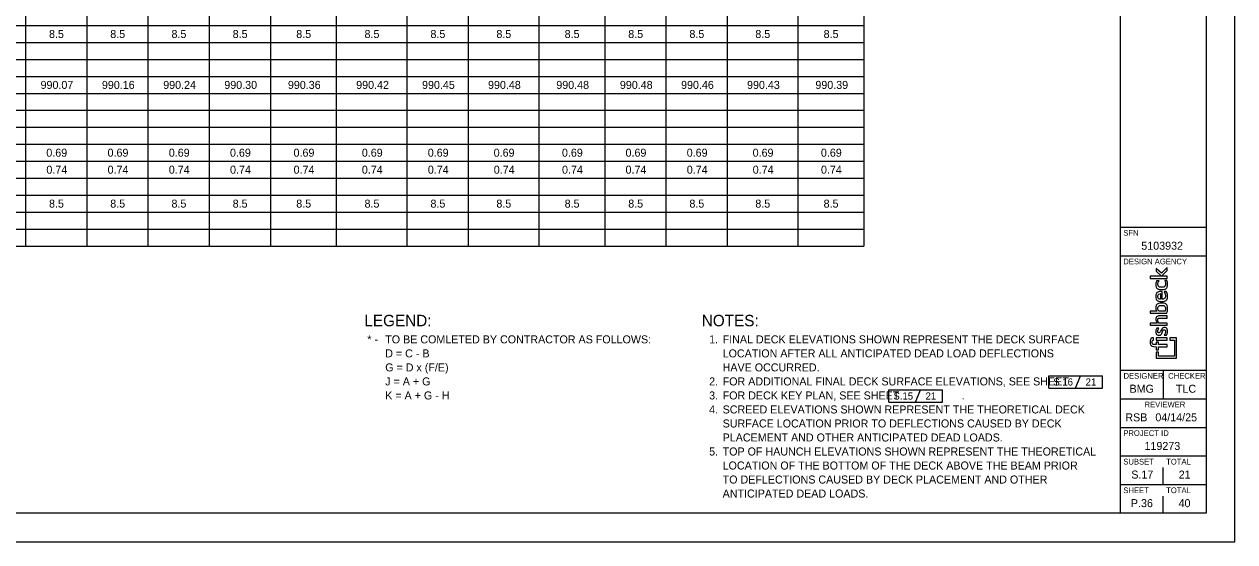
# Model space of a CAD drawing. Extents: x 0 to 34, y 0 to 22.
# Drawn here: x 12.83 to 34, y 0 to 9.05 of the extents above; entities that cross this region are included whole.
import ezdxf

# ---------------------------------------------------------------- set-up
doc = ezdxf.new("R2010")
doc.units = 0
for name, color, linetype in [('BR_P_Gen_Text', 7, 'Continuous'), ('SH_Border', 7, 'Continuous'), ('SH_Cut_Line', 7, 'Continuous'), ('SH_Data', 7, 'Continuous')]:
    doc.layers.add(name, color=color, linetype=linetype)

msp = doc.modelspace()

# ---------------------------------------------------------------- linework, layer by layer
at = {"layer": 'BR_P_Gen_Text'}
for p, q in [((27.51, 20.916), (27.51, 5.17)), ((12.851, 20.57), (12.851, 5.17)), ((13.921, 20.273), (13.921, 5.17)), ((14.992, 20.273), (14.992, 5.17)), ((16.063, 20.273), (16.063, 5.17)), ((17.133, 20.273), (17.133, 5.17)), ((18.286, 20.273), (18.286, 5.17)), ((19.521, 20.273), (19.521, 5.17)), ((20.592, 20.273), (20.592, 5.17)), ((21.827, 20.273), (21.827, 5.17)), ((22.98, 20.273), (22.98, 5.17)), ((24.051, 20.273), (24.051, 5.17)), ((25.121, 20.273), (25.121, 5.17)), ((26.357, 20.273), (26.357, 5.17)), ((6.641, 9.024), (27.51, 9.024)), ((6.641, 8.728), (27.51, 8.728)), ((6.641, 8.431), (27.51, 8.431)), ((6.131, 8.135), (27.51, 8.135)), ((6.641, 7.838), (27.51, 7.838)), ((6.641, 7.542), (27.51, 7.542)), ((6.641, 7.245), (27.51, 7.245)), ((6.641, 6.949), (27.51, 6.949)), ((6.641, 6.652), (27.51, 6.652)), ((6.641, 6.356), (27.51, 6.356)), ((6.641, 6.059), (27.51, 6.059)), ((6.641, 5.763), (27.51, 5.763)), ((6.641, 5.466), (27.51, 5.466)), ((6.131, 5.17), (27.51, 5.17)), ((30.746, 2.903), (31.688, 2.903)), ((30.746, 2.685), (30.746, 2.903)), ((31.212, 2.685), (31.302, 2.903)), ((31.688, 2.685), (31.688, 2.903)), ((27.947, 2.657), (28.89, 2.657)), ((27.947, 2.44), (27.947, 2.657)), ((28.414, 2.44), (28.504, 2.657)), ((28.89, 2.44), (28.89, 2.657)), ((30.746, 2.685), (31.688, 2.685)), ((27.947, 2.44), (28.89, 2.44))]:
    msp.add_line(p, q, dxfattribs=at)
at = {"layer": 'SH_Border'}
for p, q in [((32, 0.5), (32, 21.5)), ((32, 5.5), (33.5, 5.5)), ((32, 5), (33.5, 5)), ((32, 3), (33.5, 3)), ((32.75, 3), (32.75, 2.5)), ((32, 2.5), (33.5, 2.5)), ((32, 2), (33.5, 2)), ((32, 1.5), (33.5, 1.5)), ((32, 1), (33.5, 1))]:
    msp.add_line(p, q, dxfattribs=at)
msp.add_lwpolyline([(1.5, 21.5), (33.5, 21.5), (33.5, 0.5), (1.5, 0.5)], close=True, dxfattribs=at)
at = {"layer": 'SH_Cut_Line'}
msp.add_lwpolyline([(0, 0), (34, 0), (34, 22), (0, 22)], close=True, dxfattribs=at)
at = {"layer": 'SH_Data'}
for p, q in [((32.623, 4.777), (32.623, 4.73)), ((32.72, 4.693), (32.623, 4.777)), ((32.623, 4.73), (32.72, 4.643)), ((32.82, 4.794), (32.72, 4.693)), ((32.72, 4.643), (32.82, 4.742)), ((32.82, 4.742), (32.82, 4.794)), ((32.522, 4.642), (32.522, 4.603)), ((32.82, 4.642), (32.522, 4.642)), ((32.522, 4.603), (32.82, 4.603)), ((32.675, 4.562), (32.633, 4.562)), ((32.812, 4.566), (32.774, 4.566)), ((32.82, 4.603), (32.82, 4.642)), ((32.702, 4.337), (32.702, 4.239)), ((32.727, 4.238), (32.727, 4.376)), ((32.8, 4.372), (32.763, 4.372)), ((32.781, 4.033), (32.675, 4.033)), ((32.75, 4), (32.75, 4)), ((32.674, 3.735), (32.636, 3.735)), ((32.764, 3.611), (32.806, 3.611)), ((32.58, 3.527), (32.58, 3.566)), ((32.623, 3.566), (32.623, 3.527)), ((32.82, 3.566), (32.623, 3.566)), ((32.623, 3.527), (32.82, 3.527)), ((32.82, 3.527), (32.82, 3.566)), ((32.982, 3.566), (32.863, 3.566)), ((32.863, 3.566), (32.863, 3.527)), ((32.863, 3.527), (32.943, 3.527)), ((32.943, 3.527), (32.943, 3.246)), ((32.982, 3.207), (32.982, 3.566)), ((32.663, 3.313), (32.624, 3.313)), ((32.624, 3.313), (32.624, 3.207)), ((32.624, 3.207), (32.982, 3.207)), ((32.663, 3.246), (32.663, 3.313)), ((32.943, 3.246), (32.663, 3.246)), ((32.75, 1), (32.75, 1.3)), ((32.375, 0.675), (32.375, 0.675)), ((32.75, 0.5), (32.75, 0.8))]:
    msp.add_line(p, q, dxfattribs=at)
for points in [[(32.637, 4.033), (32.522, 4.033), (32.522, 3.994), (32.809, 3.994)], [(32.649, 3.824), (32.649, 3.823), (32.522, 3.823), (32.522, 3.784), (32.82, 3.784), (32.82, 3.823), (32.679, 3.823)], [(32.698, 3.911), (32.82, 3.911), (32.82, 3.949), (32.699, 3.949)], [(32.623, 3.409), (32.623, 3.357), (32.663, 3.357), (32.663, 3.409), (32.82, 3.409), (32.82, 3.448), (32.663, 3.448), (32.663, 3.492), (32.623, 3.492), (32.623, 3.448)]]:
    msp.add_lwpolyline(points, dxfattribs=at)
for points in [[(32.633, 4.562), (32.625, 4.543), (32.62, 4.528), (32.62, 4.505), (32.62, 4.446), (32.661, 4.408), (32.725, 4.408), (32.783, 4.408), (32.824, 4.449), (32.824, 4.508), (32.824, 4.528), (32.818, 4.553), (32.812, 4.566)], [(32.774, 4.566), (32.782, 4.547), (32.787, 4.531), (32.787, 4.514), (32.787, 4.474), (32.762, 4.448), (32.722, 4.448), (32.682, 4.448), (32.655, 4.472), (32.655, 4.508), (32.655, 4.525), (32.66, 4.54), (32.675, 4.562)], [(32.727, 4.376), (32.655, 4.376), (32.62, 4.343), (32.62, 4.291), (32.62, 4.236), (32.66, 4.199), (32.719, 4.199), (32.773, 4.199), (32.824, 4.233), (32.824, 4.294), (32.824, 4.327), (32.816, 4.349), (32.8, 4.372)], [(32.702, 4.239), (32.671, 4.244), (32.653, 4.262), (32.653, 4.291), (32.653, 4.319), (32.672, 4.336), (32.702, 4.337)], [(32.763, 4.372), (32.778, 4.35), (32.786, 4.327), (32.786, 4.304), (32.786, 4.266), (32.766, 4.244), (32.727, 4.238)], [(32.809, 3.994), (32.818, 4.013), (32.824, 4.041), (32.824, 4.067), (32.824, 4.133), (32.784, 4.172), (32.717, 4.172), (32.661, 4.172), (32.62, 4.136), (32.62, 4.087), (32.62, 4.068), (32.625, 4.05), (32.637, 4.033)], [(32.675, 4.033), (32.66, 4.05), (32.654, 4.061), (32.654, 4.078), (32.654, 4.11), (32.682, 4.132), (32.723, 4.132), (32.76, 4.132), (32.787, 4.107), (32.787, 4.072), (32.787, 4.061), (32.784, 4.044), (32.781, 4.033)], [(32.699, 3.949), (32.646, 3.949), (32.62, 3.921), (32.62, 3.883), (32.62, 3.861), (32.63, 3.839), (32.649, 3.824)], [(32.679, 3.823), (32.658, 3.842), (32.651, 3.855), (32.651, 3.872), (32.651, 3.896), (32.669, 3.911), (32.698, 3.911)], [(32.636, 3.735), (32.625, 3.714), (32.62, 3.695), (32.62, 3.677), (32.62, 3.638), (32.64, 3.612), (32.673, 3.612), (32.726, 3.612), (32.74, 3.704), (32.767, 3.704), (32.781, 3.704), (32.789, 3.691), (32.789, 3.675), (32.789, 3.659), (32.781, 3.636), (32.764, 3.611)], [(32.806, 3.611), (32.819, 3.636), (32.824, 3.655), (32.824, 3.679), (32.824, 3.716), (32.8, 3.744), (32.766, 3.744), (32.746, 3.744), (32.732, 3.732), (32.711, 3.7), (32.691, 3.665), (32.68, 3.652), (32.672, 3.652), (32.661, 3.652), (32.654, 3.662), (32.654, 3.678), (32.654, 3.692), (32.66, 3.713), (32.674, 3.735)], [(32.58, 3.566), (32.542, 3.565), (32.518, 3.536), (32.518, 3.492), (32.518, 3.439), (32.551, 3.408), (32.623, 3.409)], [(32.623, 3.448), (32.576, 3.445), (32.553, 3.461), (32.553, 3.492), (32.553, 3.509), (32.561, 3.52), (32.58, 3.527)]]:
    msp.add_open_spline(points, degree=3, dxfattribs=at)

# ---------------------------------------------------------------- texts
at = {"layer": 'BR_P_Gen_Text'}
for s, height, p in [('8.5', 0.14, (13.262, 8.806)), ('8.5', 0.14, (14.333, 8.806)), ('8.5', 0.14, (15.404, 8.806)), ('8.5', 0.14, (16.474, 8.806)), ('8.5', 0.14, (17.586, 8.806)), ('8.5', 0.14, (18.78, 8.806)), ('8.5', 0.14, (19.933, 8.806)), ('8.5', 0.14, (21.086, 8.806)), ('8.5', 0.14, (22.28, 8.806)), ('8.5', 0.14, (23.392, 8.806)), ('8.5', 0.14, (24.462, 8.806)), ('8.5', 0.14, (25.615, 8.806)), ('8.5', 0.14, (26.809, 8.806)), ('990.07', 0.14, (13.114, 7.916)), ('990.16', 0.14, (14.187, 7.916)), ('990.24', 0.14, (15.259, 7.916)), ('990.30', 0.14, (16.328, 7.916)), ('990.36', 0.14, (17.44, 7.916)), ('990.42', 0.14, (18.634, 7.916)), ('990.45', 0.14, (19.786, 7.916)), ('990.48', 0.14, (20.94, 7.916)), ('990.48', 0.14, (22.134, 7.916)), ('990.48', 0.14, (23.246, 7.916)), ('990.46', 0.14, (24.316, 7.916)), ('990.43', 0.14, (25.47, 7.916)), ('990.39', 0.14, (26.665, 7.916)), ('0.69', 0.14, (13.215, 6.731)), ('0.69', 0.14, (14.286, 6.731)), ('0.69', 0.14, (15.357, 6.731)), ('0.69', 0.14, (16.427, 6.731)), ('0.69', 0.14, (17.539, 6.731)), ('0.69', 0.14, (18.733, 6.731)), ('0.69', 0.14, (19.886, 6.731)), ('0.69', 0.14, (21.039, 6.731)), ('0.69', 0.14, (22.233, 6.731)), ('0.69', 0.14, (23.345, 6.731)), ('0.69', 0.14, (24.415, 6.731)), ('0.69', 0.14, (25.568, 6.731)), ('0.69', 0.14, (26.762, 6.731)), ('0.74', 0.14, (13.216, 6.434)), ('0.74', 0.14, (14.287, 6.434)), ('0.74', 0.14, (15.357, 6.434)), ('0.74', 0.14, (16.428, 6.434)), ('0.74', 0.14, (17.54, 6.434)), ('0.74', 0.14, (18.734, 6.434)), ('0.74', 0.14, (19.887, 6.434)), ('0.74', 0.14, (21.04, 6.434)), ('0.74', 0.14, (22.234, 6.434)), ('0.74', 0.14, (23.345, 6.434)), ('0.74', 0.14, (24.416, 6.434)), ('0.74', 0.14, (25.569, 6.434)), ('0.74', 0.14, (26.763, 6.434)), ('8.5', 0.14, (13.262, 5.841)), ('8.5', 0.14, (14.333, 5.841)), ('8.5', 0.14, (15.404, 5.841)), ('8.5', 0.14, (16.474, 5.841)), ('8.5', 0.14, (17.586, 5.841)), ('8.5', 0.14, (18.78, 5.841)), ('8.5', 0.14, (19.933, 5.841)), ('8.5', 0.14, (21.086, 5.841)), ('8.5', 0.14, (22.28, 5.841)), ('8.5', 0.14, (23.392, 5.841)), ('8.5', 0.14, (24.462, 5.841)), ('8.5', 0.14, (25.615, 5.841)), ('8.5', 0.14, (26.809, 5.841)), ('LEGEND:', 0.2, (18.777, 3.767)), ('NOTES:', 0.2, (24.678, 3.767)), ('* -', 0.14, (18.829, 3.468)), ('TO BE COMLETED BY CONTRACTOR AS FOLLOWS:', 0.14, (19.142, 3.468)), ('1.', 0.14, (24.807, 3.468)), ('FINAL DECK ELEVATIONS SHOWN REPRESENT THE DECK SURFACE', 0.14, (25.043, 3.468)), ('D = C - B', 0.14, (19.142, 3.223)), ('LOCATION AFTER ALL ANTICIPATED DEAD LOAD DEFLECTIONS', 0.14, (25.043, 3.223)), ('G = D x (F/E)', 0.14, (19.142, 2.978)), ('HAVE OCCURRED. ', 0.14, (25.043, 2.978)), ('J = A + G', 0.14, (19.142, 2.733)), ('2.', 0.14, (24.807, 2.733)), ('FOR ADDITIONAL FINAL DECK SURFACE ELEVATIONS, SEE SHEET                     .', 0.14, (25.043, 2.733)), ('S.16', 0.125, (30.826, 2.731)), ('21', 0.125, (31.391, 2.731)), ('K = A + G - H', 0.14, (19.142, 2.488)), ('3.', 0.14, (24.807, 2.488)), ('FOR DECK KEY PLAN, SEE SHEET                     .', 0.14, (25.043, 2.488)), ('S.15', 0.125, (28.03, 2.486)), ('21', 0.125, (28.592, 2.486)), ('4.', 0.14, (24.807, 2.243)), ('SCREED ELEVATIONS SHOWN REPRESENT THE THEORETICAL DECK', 0.14, (25.043, 2.243)), ('SURFACE LOCATION PRIOR TO DEFLECTIONS CAUSED BY DECK', 0.14, (25.043, 1.998)), ('PLACEMENT AND OTHER ANTICIPATED DEAD LOADS.', 0.14, (25.043, 1.753)), ('5.', 0.14, (24.807, 1.508)), ('TOP OF HAUNCH ELEVATIONS SHOWN REPRESENT THE THEORETICAL', 0.14, (25.043, 1.508)), ('LOCATION OF THE BOTTOM OF THE DECK ABOVE THE BEAM PRIOR', 0.14, (25.043, 1.263)), ('TO DEFLECTIONS CAUSED BY DECK PLACEMENT AND OTHER', 0.14, (25.043, 1.018)), ('ANTICIPATED DEAD LOADS.', 0.14, (25.043, 0.773))]:
    msp.add_text(s, height=height, dxfattribs=at).set_placement(p)
at = {"layer": 'SH_Data'}
for s, height, p in [('SFN', 0.1, (32.05, 5.35)), ('5103932', 0.14, (32.365, 5.105)), ('DESIGN AGENCY', 0.1, (32.05, 4.85)), ('DESIGNER', 0.1, (32.054, 2.85)), ('CHECKER', 0.1, (32.835, 2.85)), ('BMG', 0.14, (32.159, 2.605)), ('TLC', 0.14, (32.97, 2.605)), ('REVIEWER', 0.1, (32.422, 2.35)), ('RSB', 0.14, (32.086, 2.105)), ('04/14/25', 0.14, (32.611, 2.105)), ('PROJECT ID', 0.1, (32.05, 1.85)), ('119273', 0.14, (32.421, 1.605)), ('SUBSET', 0.1, (32.05, 1.35)), ('TOTAL', 0.1, (32.8, 1.35)), ('S.17', 0.14, (32.19, 1.105)), ('21', 0.14, (33.019, 1.105)), ('SHEET', 0.1, (32.05, 0.85)), ('TOTAL', 0.1, (32.8, 0.85)), ('P.36', 0.14, (32.183, 0.605)), ('40', 0.14, (33.017, 0.605))]:
    msp.add_text(s, height=height, dxfattribs=at).set_placement(p)

doc.saveas('drawing.dxf')
